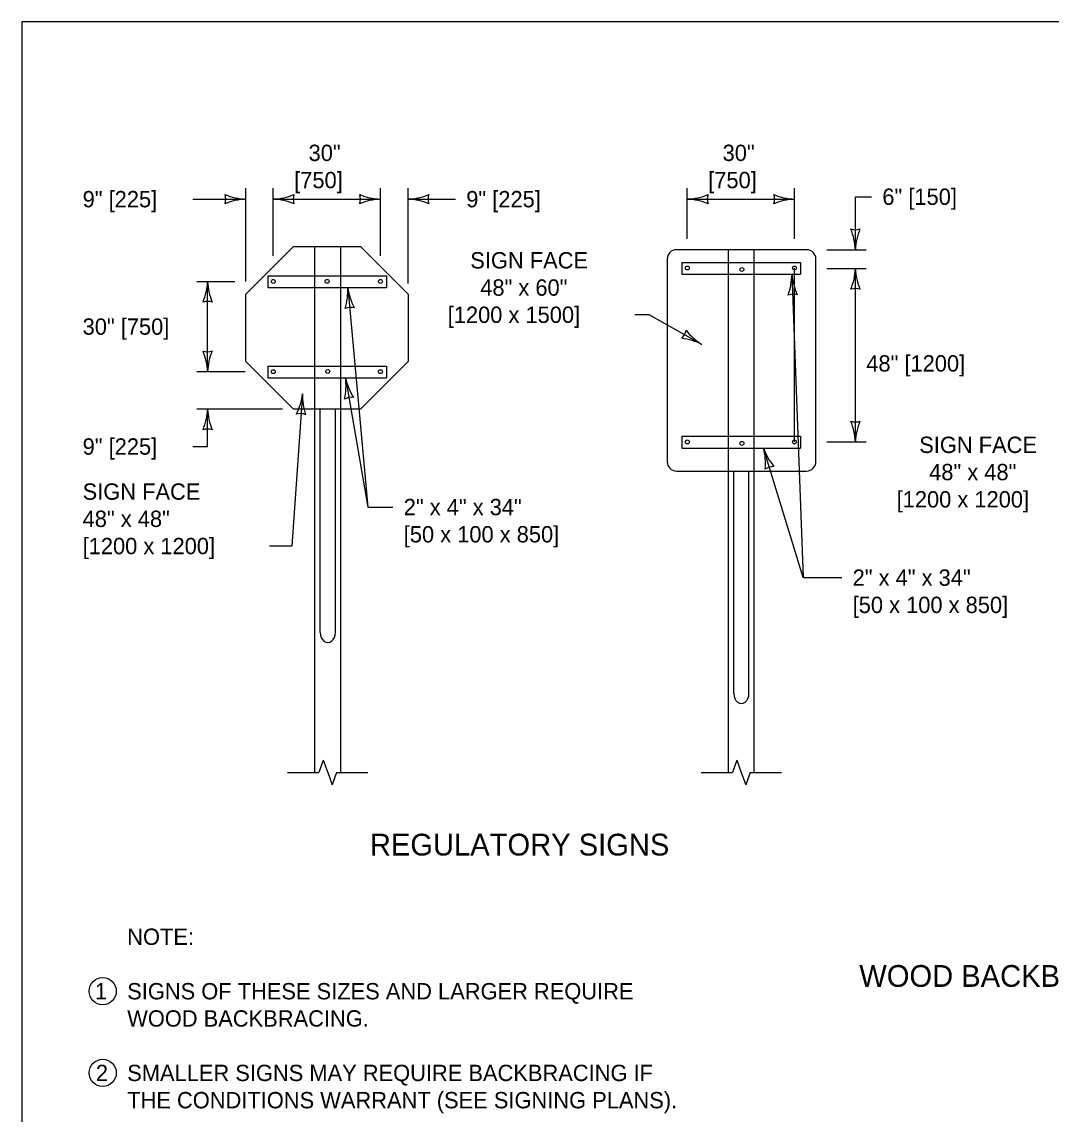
# Model space of a CAD drawing. Extents: x 49991.4 to 50021, y 49987.6 to 50011.4.
# Drawn here: x 50000.336 to 50004.115, y 50007.252 to 50011.263 of the extents above; entities that cross this region are included whole.
import ezdxf

# ---------------------------------------------------------------- set-up
doc = ezdxf.new("R2010")
doc.units = 0
for name, color, linetype in [('Level 1', 7, 'Continuous'), ('Level 2', 7, 'Continuous'), ('Level 3', 7, 'Continuous'), ('Level 4', 7, 'Continuous'), ('Level 6', 7, 'Continuous')]:
    doc.layers.add(name, color=color, linetype=linetype)

msp = doc.modelspace()

# ---------------------------------------------------------------- linework, layer by layer
at = {"layer": 'Level 1'}
for p, q in [((50001.1578, 50010.2627), (50001.3325, 50010.4374)), ((50001.3325, 50010.4374), (50001.5794, 50010.4374)), ((50001.5794, 50010.4374), (50001.754, 50010.2627)), ((50003.2171, 50010.4262), (50002.7393, 50010.4262)), ((50002.7053, 50010.3922), (50002.7053, 50009.6477)), ((50003.2511, 50009.6477), (50003.2511, 50010.3922)), ((50001.1578, 50010.0158), (50001.1578, 50010.2627)), ((50001.754, 50010.2627), (50001.754, 50010.0158)), ((50001.3325, 50009.8412), (50001.1578, 50010.0158)), ((50001.754, 50010.0158), (50001.5794, 50009.8412)), ((50001.5794, 50009.8412), (50001.3325, 50009.8412)), ((50001.4111, 50008.5067), (50001.4111, 50009.8412)), ((50001.4309, 50009.0207), (50001.4309, 50009.8412)), ((50001.4869, 50009.0207), (50001.4869, 50009.8412)), ((50001.5063, 50008.5067), (50001.5063, 50009.8412)), ((50002.7393, 50009.6137), (50003.2171, 50009.6137)), ((50002.9298, 50008.5067), (50002.9298, 50009.6137)), ((50002.9496, 50008.7968), (50002.9496, 50009.6137)), ((50003.0056, 50008.7968), (50003.0056, 50009.6137)), ((50003.025, 50008.5067), (50003.025, 50009.6137))]:
    msp.add_line(p, q, dxfattribs=at)
msp.add_lwpolyline([(50008.6146, 50011.2628), (50000.3356, 50011.2628), (50000.3356, 50000.0624), (50008.6146, 50000.0624)], close=True, dxfattribs=at)
for centre in [(50002.7791, 50010.359), (50002.9795, 50010.3536), (50003.1727, 50010.359), (50001.2588, 50010.3097), (50001.4566, 50010.31), (50001.6524, 50010.3097), (50001.2588, 50009.9783), (50001.4588, 50009.9791), (50001.6524, 50009.9783), (50002.7791, 50009.7205), (50002.9795, 50009.7151), (50003.1727, 50009.7205)]:
    msp.add_circle(centre, 0.0072, dxfattribs=at)
for centre, start, end in [((50002.7394, 50010.3922), 90, 180), ((50003.2171, 50010.3922), 0, 90), ((50002.7393, 50009.6477), 180, 270), ((50003.2171, 50009.6477), 270, 0)]:
    msp.add_arc(centre, 0.034, start, end, dxfattribs=at)
for centre in [(50001.4589, 50009.0207), (50002.9776, 50008.7968)]:
    msp.add_ellipse(centre, major_axis=(0, -0.0368), ratio=0.761048, start_param=4.712389, end_param=7.853982, dxfattribs=at)
at = {"layer": 'Level 2'}
for centre in [(50000.6325, 50007.7037), (50000.6325, 50007.4037)]:
    msp.add_circle(centre, 0.05, dxfattribs=at)
at = {"layer": 'Level 3'}
for p, q in [((50001.1578, 50010.3097), (50001.1578, 50010.6518)), ((50001.2588, 50010.4037), (50001.2588, 50010.6518)), ((50001.6524, 50010.4037), (50001.6524, 50010.6518)), ((50001.754, 50010.3027), (50001.754, 50010.6518)), ((50002.7791, 50010.4662), (50002.7791, 50010.6518)), ((50003.1727, 50010.4662), (50003.1727, 50010.6518)), ((50003.3963, 50010.4277), (50003.3963, 50010.6207)), ((50003.3963, 50010.6207), (50003.4552, 50010.6207)), ((50000.9637, 50010.6118), (50001.1578, 50010.6118)), ((50001.2588, 50010.6118), (50001.6524, 50010.6118)), ((50001.7545, 50010.6118), (50001.9274, 50010.6118)), ((50002.7791, 50010.6118), (50003.1727, 50010.6118)), ((50003.2911, 50010.4262), (50003.4363, 50010.4262)), ((50003.1631, 50010.3364), (50003.2048, 50009.2222)), ((50003.1727, 50009.7205), (50003.1727, 50010.359)), ((50003.2911, 50010.357), (50003.4363, 50010.357)), ((50003.3963, 50009.7206), (50003.3963, 50010.357)), ((50000.9776, 50010.3097), (50001.1178, 50010.3097)), ((50001.0176, 50009.9782), (50001.0176, 50010.3097)), ((50001.5324, 50010.2871), (50001.6066, 50009.4814)), ((50002.6394, 50010.1873), (50002.5859, 50010.1873)), ((50002.8328, 50010.0782), (50002.6394, 50010.1873)), ((50001.1554, 50009.9782), (50000.9776, 50009.9782)), ((50001.524, 50009.9557), (50001.6066, 50009.4814)), ((50001.3662, 50009.8975), (50001.3274, 50009.3382)), ((50001.2925, 50009.8412), (50000.9776, 50009.8412)), ((50001.0176, 50009.7036), (50001.0176, 50009.8412)), ((50000.9637, 50009.7036), (50001.0176, 50009.7036)), ((50003.2048, 50009.2222), (50003.0589, 50009.6979)), ((50003.2911, 50009.7206), (50003.4363, 50009.7206)), ((50001.6066, 50009.4814), (50001.6979, 50009.4814)), ((50001.3274, 50009.3382), (50001.2453, 50009.3382)), ((50003.2048, 50009.2222), (50003.3462, 50009.2222))]:
    msp.add_line(p, q, dxfattribs=at)
for centre, radius, start, end in [((50001.167, 50010.8339), 0.2223, 247.456, 267.6395), ((50001.0296, 50010.6118), 0.0548, 342.1388, 17.8612), ((50001.2473, 50010.8445), 0.233, 272.8273, 292.0772), ((50001.387, 50010.6118), 0.0548, 162.1388, 197.8612), ((50001.6616, 50010.8339), 0.2223, 247.456, 267.6395), ((50001.5242, 50010.6118), 0.0548, 342.1388, 17.8612), ((50001.7425, 50010.8445), 0.233, 272.8273, 292.0772), ((50001.8822, 50010.6118), 0.0548, 162.1388, 197.8612), ((50002.7676, 50010.8445), 0.233, 272.8273, 292.0772), ((50002.9073, 50010.6118), 0.0548, 162.1388, 197.8612), ((50003.1819, 50010.8339), 0.2223, 247.456, 267.6395), ((50003.0445, 50010.6118), 0.0548, 342.1388, 17.8612), ((50001.1693, 50010.3791), 0.233, 92.8273, 112.0772), ((50001.2496, 50010.3897), 0.2223, 67.456, 87.6395), ((50001.6639, 50010.3791), 0.233, 92.8273, 112.0772), ((50001.7448, 50010.3897), 0.2223, 67.456, 87.6395), ((50002.7699, 50010.3897), 0.2223, 67.456, 87.6395), ((50003.1842, 50010.3791), 0.233, 92.8273, 112.0772), ((50003.3963, 50010.5544), 0.0548, 252.1388, 287.8612), ((50003.1636, 50010.4147), 0.233, 2.8273, 22.0772), ((50003.6184, 50010.4171), 0.2223, 157.456, 177.6395), ((50002.9408, 50010.3372), 0.2223, 339.5994, 359.7829), ((50003.3952, 50010.3566), 0.233, 184.9707, 204.2205), ((50003.1742, 50010.3662), 0.2223, 337.456, 357.6395), ((50003.629, 50010.3685), 0.233, 182.8273, 202.0772), ((50000.7955, 50010.3189), 0.2223, 337.456, 357.6395), ((50001.2503, 50010.3212), 0.233, 182.8273, 202.0772), ((50001.3104, 50010.2758), 0.2223, 342.7178, 2.9013), ((50001.7631, 50010.3199), 0.233, 188.0891, 207.3389), ((50003.1679, 50010.2083), 0.0548, 74.2822, 110.0045), ((50003.3963, 50010.2288), 0.0548, 72.1388, 107.8612), ((50001.0176, 50010.1815), 0.0548, 72.1388, 107.8612), ((50001.5442, 50010.1594), 0.0548, 77.4006, 113.1229), ((50002.7211, 50010.1412), 0.0548, 312.7108, 348.4331), ((50002.7285, 50009.8699), 0.233, 63.3993, 82.6491), ((50002.9499, 50010.2672), 0.2223, 218.028, 238.2115), ((50001.0176, 50010.1064), 0.0548, 252.1388, 287.8612), ((50000.7849, 50009.9667), 0.233, 2.8273, 22.0772), ((50001.2397, 50009.9691), 0.2223, 157.456, 177.6395), ((50001.3036, 50009.9266), 0.2223, 347.3351, 7.5186), ((50001.7513, 50010.0069), 0.233, 192.7064, 211.9562), ((50001.1452, 50009.922), 0.2223, 333.4876, 353.6711), ((50001.5991, 50009.8929), 0.233, 178.8589, 198.1088), ((50001.546, 50009.8294), 0.0548, 82.0179, 117.7402), ((50000.7955, 50009.8504), 0.2223, 337.456, 357.6395), ((50001.2503, 50009.8527), 0.233, 182.8273, 202.0772), ((50001.3573, 50009.7696), 0.0548, 68.1704, 103.8928), ((50003.3963, 50009.8488), 0.0548, 252.1388, 287.8612), ((50003.1636, 50009.7091), 0.233, 2.8273, 22.0772), ((50003.6184, 50009.7114), 0.2223, 157.456, 177.6395), ((50001.0176, 50009.713), 0.0548, 72.1388, 107.8612), ((50002.8439, 50009.6414), 0.2223, 354.5352, 14.7187), ((50003.278, 50009.7772), 0.233, 199.9065, 219.1563), ((50003.0966, 50009.5753), 0.0548, 89.218, 124.9403)]:
    msp.add_arc(centre, radius, start, end, dxfattribs=at)
at = {"layer": 'Level 4'}
for p, q in [((50001.4111, 50009.8412), (50001.4111, 50010.4374)), ((50001.5063, 50009.8412), (50001.5063, 50010.4374)), ((50002.9298, 50009.6137), (50002.9298, 50010.4262)), ((50003.025, 50009.6137), (50003.025, 50010.4262)), ((50002.7592, 50010.3797), (50002.7592, 50010.3364)), ((50002.7592, 50010.3797), (50003.1943, 50010.3797)), ((50003.1943, 50010.3797), (50003.1943, 50010.3364)), ((50002.7592, 50010.3364), (50003.1943, 50010.3364)), ((50001.2389, 50010.3304), (50001.2389, 50010.2871)), ((50001.2389, 50010.3304), (50001.674, 50010.3304)), ((50001.674, 50010.3304), (50001.674, 50010.2871)), ((50001.2389, 50010.2871), (50001.674, 50010.2871)), ((50001.2389, 50009.999), (50001.2389, 50009.9557)), ((50001.2389, 50009.999), (50001.674, 50009.999)), ((50001.674, 50009.999), (50001.674, 50009.9557)), ((50001.2389, 50009.9557), (50001.674, 50009.9557)), ((50002.7592, 50009.7412), (50002.7592, 50009.6979)), ((50002.7592, 50009.7412), (50003.1943, 50009.7412)), ((50003.1943, 50009.7412), (50003.1943, 50009.6979)), ((50002.7592, 50009.6979), (50003.1943, 50009.6979))]:
    msp.add_line(p, q, dxfattribs=at)
at = {"layer": 'Level 6'}
for p, q in [((50001.4425, 50008.5524), (50001.4263, 50008.5067)), ((50001.4425, 50008.5524), (50001.4587, 50008.5067)), ((50002.9612, 50008.5524), (50002.945, 50008.5067)), ((50002.9612, 50008.5524), (50002.9774, 50008.5067)), ((50001.3111, 50008.5067), (50001.4263, 50008.5067)), ((50001.4587, 50008.5067), (50001.4749, 50008.461)), ((50001.4911, 50008.5067), (50001.4749, 50008.461)), ((50001.4911, 50008.5067), (50001.6063, 50008.5067)), ((50002.8298, 50008.5067), (50002.945, 50008.5067)), ((50002.9774, 50008.5067), (50002.9936, 50008.461)), ((50003.0098, 50008.5067), (50002.9936, 50008.461)), ((50003.0098, 50008.5067), (50003.125, 50008.5067))]:
    msp.add_line(p, q, dxfattribs=at)

# ---------------------------------------------------------------- texts
at = {"layer": 'Level 2'}
for s, height, p in [('30"', 0.06, (50001.3884, 50010.7518)), ('30"', 0.06, (50002.9087, 50010.7518)), ('[750]', 0.06, (50001.3355, 50010.6518)), ('[750]', 0.06, (50002.8558, 50010.6518)), ('9" [225]', 0.06, (50000.5588, 50010.5818)), ('9" [225]', 0.06, (50001.9674, 50010.5818)), ('6" [150]', 0.06, (50003.4952, 50010.5907)), ('SIGN FACE', 0.06, (50001.9822, 50010.3573)), ('48" x 60"', 0.06, (50002.0188, 50010.2573)), ('[1200 x 1500]', 0.06, (50001.8993, 50010.1573)), ('30" [750]', 0.06, (50000.5588, 50010.114)), ('48" [1200]', 0.06, (50003.4363, 50009.9788)), ('9" [225]', 0.06, (50000.5588, 50009.6736)), ('SIGN FACE', 0.06, (50003.6306, 50009.6798)), ('48" x 48"', 0.06, (50003.6672, 50009.5798)), ('SIGN FACE', 0.06, (50000.5588, 50009.5082)), ('[1200 x 1200]', 0.06, (50003.5477, 50009.4798)), ('2" x 4" x 34"', 0.06, (50001.7379, 50009.4514)), ('48" x 48"', 0.06, (50000.5588, 50009.4082)), ('[50 x 100 x 850]', 0.06, (50001.7379, 50009.3514)), ('[1200 x 1200]', 0.06, (50000.5588, 50009.3082)), ('2" x 4" x 34"', 0.06, (50003.3862, 50009.1922)), ('[50 x 100 x 850]', 0.06, (50003.3862, 50009.0922)), ('REGULATORY SIGNS', 0.08, (50001.6135, 50008.2019)), ('NOTE:', 0.06, (50000.7225, 50007.8737)), ('WOOD BACKBRACE INSTALLATIONS', 0.08, (50003.4106, 50007.7197)), ('1', 0.06, (50000.6037, 50007.6737)), ('SIGNS OF THESE SIZES AND LARGER REQUIRE', 0.06, (50000.7225, 50007.6737)), ('WOOD BACKBRACING.', 0.06, (50000.7225, 50007.5737)), ('2', 0.06, (50000.6073, 50007.3737)), ('SMALLER SIGNS MAY REQUIRE BACKBRACING IF', 0.06, (50000.7225, 50007.3737)), ('THE CONDITIONS WARRANT (SEE SIGNING PLANS).', 0.06, (50000.7225, 50007.2737))]:
    msp.add_text(s, height=height, dxfattribs=at).set_placement(p)

doc.saveas('drawing.dxf')
